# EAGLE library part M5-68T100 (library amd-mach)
AMD MACH SERIES
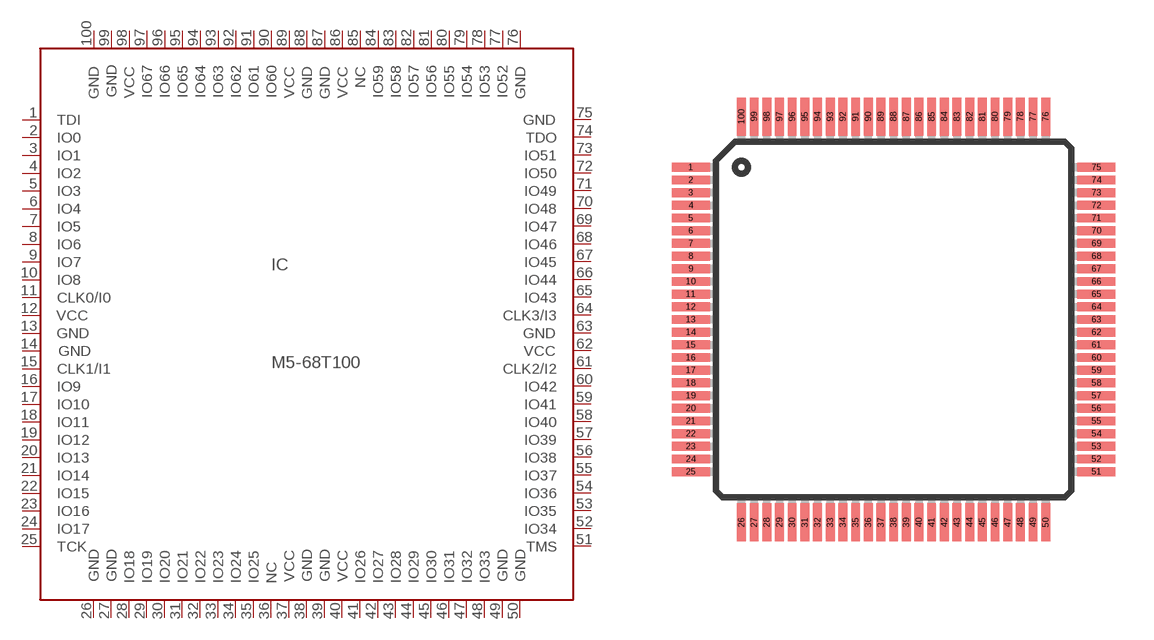
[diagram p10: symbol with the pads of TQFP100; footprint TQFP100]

Designator prefix IC

## M5-68T100 (OC_FARNELL: unknown; OC_NEWARK: unknown)  [TQFP100]
1  TDI  in
2  IO0
3  IO1
4  IO2
5  IO3
6  IO4
7  IO5
8  IO6
9  IO7
10  IO8
11  CLK0/I0  in
12  VCC  pwr
13  GND  pwr
14  GND  pwr
15  CLK1/I1  in
16  IO9
17  IO10
18  IO11
19  IO12
20  IO13
21  IO14
22  IO15
23  IO16
24  IO17
25  TCK  in
26  GND  pwr
27  GND  pwr
28  IO18
29  IO19
30  IO20
31  IO21
32  IO22
33  IO23
34  IO24
35  IO25
36  NC  nc
37  VCC  pwr
38  GND  pwr
39  GND  pwr
40  VCC  pwr
41  IO26
42  IO27
43  IO28
44  IO29
45  IO30
46  IO31
47  IO32
48  IO33
49  GND  pwr
50  GND  pwr
51  TMS  in
52  IO34
53  IO35
54  IO36
55  IO37
56  IO38
57  IO39
58  IO40
59  IO41
60  IO42
61  CLK2/I2  in
62  VCC  pwr
63  GND  pwr
64  CLK3/I3  in
65  IO43
66  IO44
67  IO45
68  IO46
69  IO47
70  IO48
71  IO49
72  IO50
73  IO51
74  TDO  out
75  GND  pwr
76  GND  pwr
77  IO52
78  IO53
79  IO54
80  IO55
81  IO56
82  IO57
83  IO58
84  IO59
85  NC1  nc
86  VCC  pwr
87  GND  pwr
88  GND  pwr
89  VCC  pwr
90  IO60
91  IO61
92  IO62
93  IO63
94  IO64
95  IO65
96  IO66
97  IO67
98  VCC  pwr
99  GND  pwr
100  GND  pwr

## Footprint TQFP100 (pad centres in mm)
THIN QUAD FLAT PACK
smd 1.5 x 0.35: 1 -8,6; 2 -8,5.5; 3 -8,5; 4 -8,4.5; 5 -8,4; 6 -8,3.5; 7 -8,3; 8 -8,2.5; 9 -8,2; 10 -8,1.5; 11 -8,1; 12 -8,0.5; 13 -8,0; 14 -8,-0.5; 15 -8,-1; 16 -8,-1.5; 17 -8,-2; 18 -8,-2.5; 19 -8,-3; 20 -8,-3.5; 21 -8,-4; 22 -8,-4.5; 23 -8,-5; 24 -8,-5.5; 25 -8,-6; 51 8,-6; 52 8,-5.5; 53 8,-5; 54 8,-4.5; 55 8,-4; 56 8,-3.5; 57 8,-3; 58 8,-2.5; 59 8,-2; 60 8,-1.5; 61 8,-1; 62 8,-0.5; 63 8,0; 64 8,0.5; 65 8,1; 66 8,1.5; 67 8,2; 68 8,2.5; 69 8,3; 70 8,3.5; 71 8,4; 72 8,4.5; 73 8,5; 74 8,5.5; 75 8,6
smd 0.35 x 1.5: 26 -6,-8; 27 -5.5,-8; 28 -5,-8; 29 -4.5,-8; 30 -4,-8; 31 -3.5,-8; 32 -3,-8; 33 -2.5,-8; 34 -2,-8; 35 -1.5,-8; 36 -1,-8; 37 -0.5,-8; 38 0,-8; 39 0.5,-8; 40 1,-8; 41 1.5,-8; 42 2,-8; 43 2.5,-8; 44 3,-8; 45 3.5,-8; 46 4,-8; 47 4.5,-8; 48 5,-8; 49 5.5,-8; 50 6,-8; 76 6,8; 77 5.5,8; 78 5,8; 79 4.5,8; 80 4,8; 81 3.5,8; 82 3,8; 83 2.5,8; 84 2,8; 85 1.5,8; 86 1,8; 87 0.5,8; 88 0,8; 89 -0.5,8; 90 -1,8; 91 -1.5,8; 92 -2,8; 93 -2.5,8; 94 -3,8; 95 -3.5,8; 96 -4,8; 97 -4.5,8; 98 -5,8; 99 -5.5,8; 100 -6,8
